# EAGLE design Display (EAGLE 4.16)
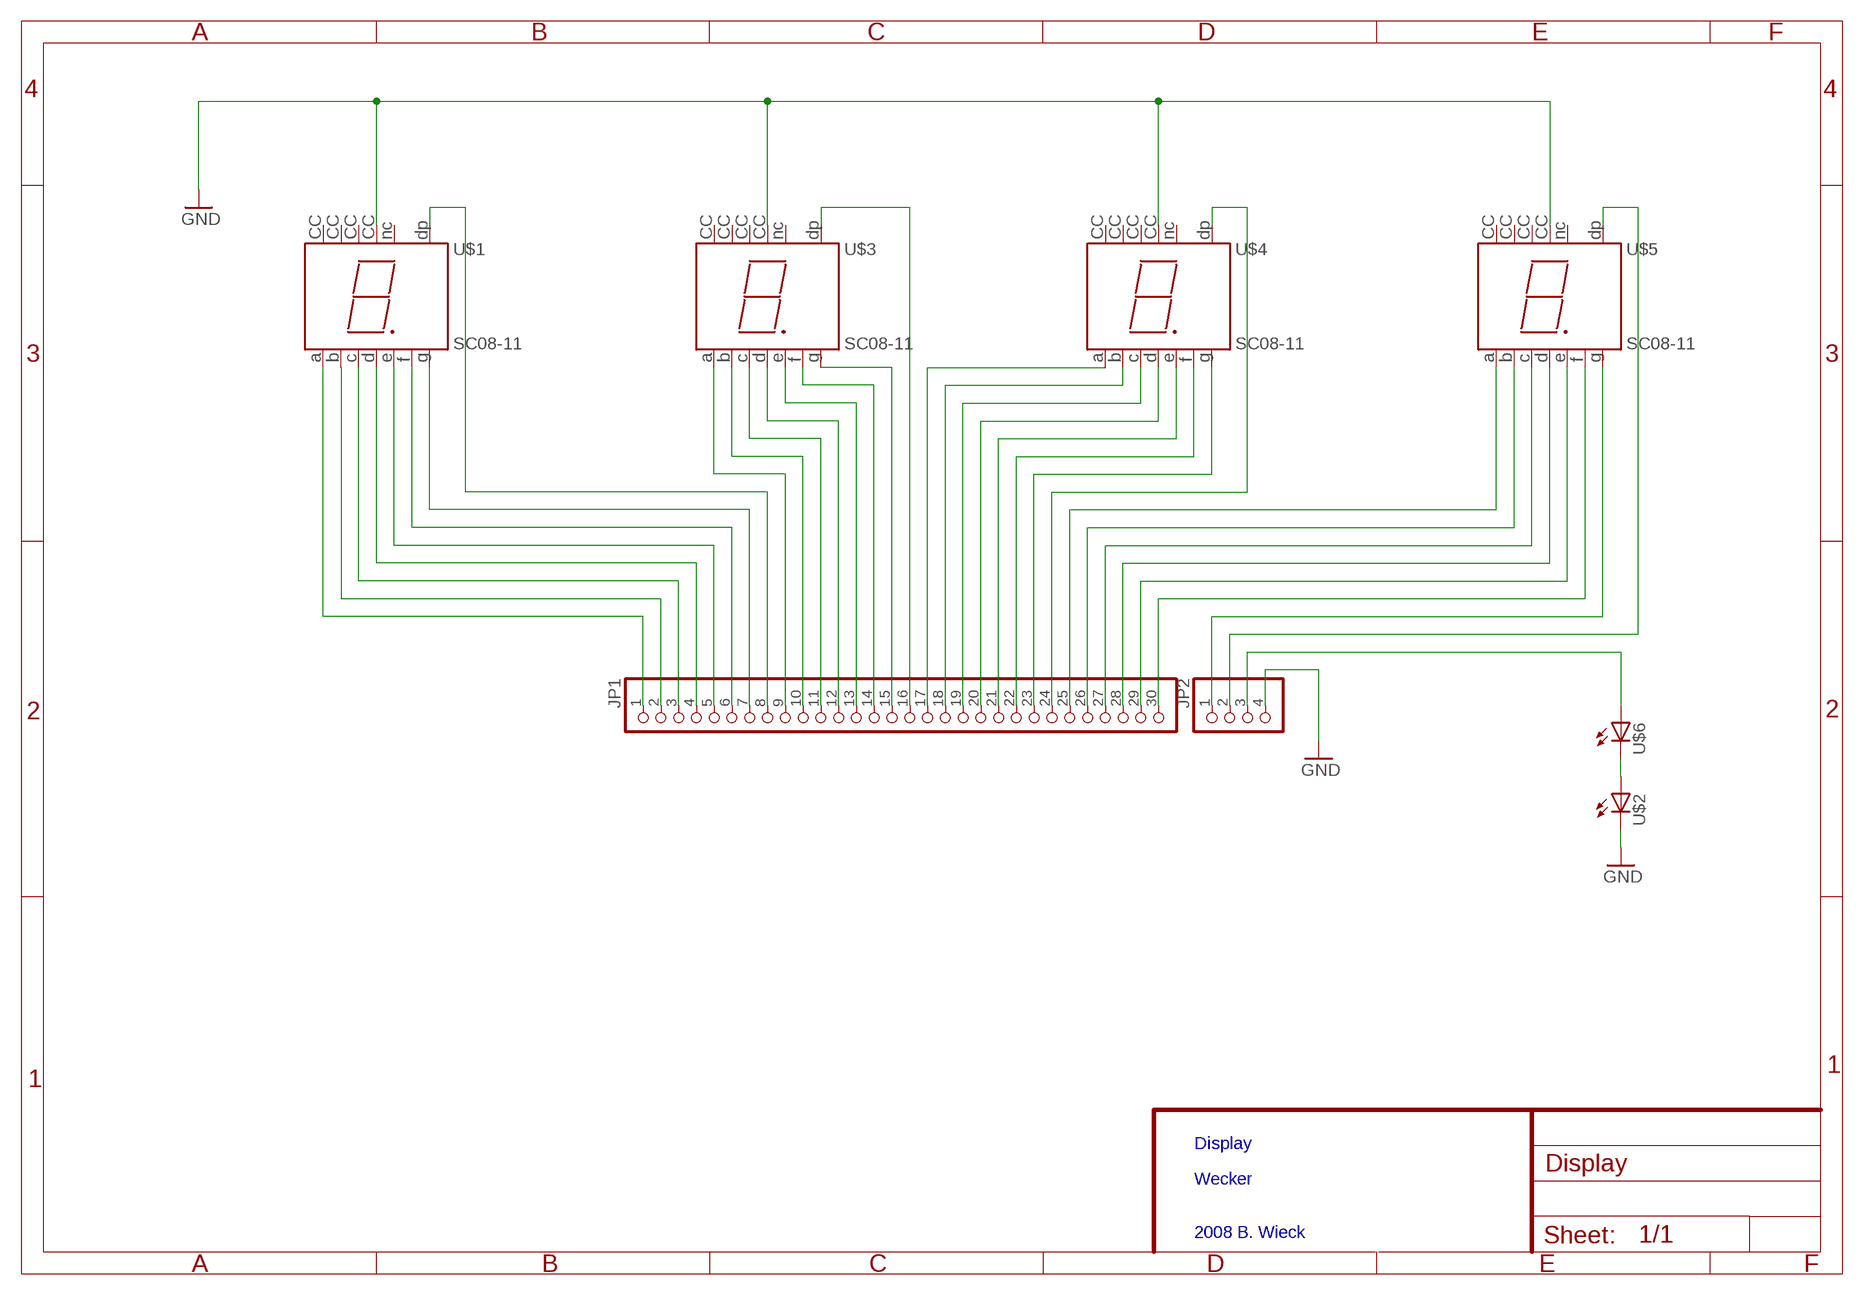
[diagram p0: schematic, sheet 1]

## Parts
JP1  PINHD-1X30  [1X30]
JP2  PINHD-1X4  [1X04]
U$1  SC08-11  [SC08]
U$2  LED3MM  [LED3MM]
U$3  SC08-11  [SC08]
U$4  SC08-11  [SC08]
U$5  SC08-11  [SC08]
U$6  LED3MM  [LED3MM]

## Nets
GND: JP2.4 U$1.CC@3(CC) U$2.K(C) U$3.CC@3(CC) U$4.CC@3(CC) U$5.CC@3(CC)
N$1: JP1.1 U$1.A
N$2: JP1.2 U$1.B
N$3: JP1.3 U$1.C
N$4: JP1.4 U$1.D
N$5: JP1.5 U$1.E
N$6: JP1.6 U$1.F
N$7: JP1.7 U$1.G
N$8: JP1.8 U$1.DP
N$9: JP1.9 U$3.A
N$10: JP1.10 U$3.B
N$11: JP1.11 U$3.C
N$12: JP1.12 U$3.D
N$13: JP1.13 U$3.E
N$14: JP1.14 U$3.F
N$15: JP1.15 U$3.G
N$16: JP1.16 U$3.DP
N$17: JP1.17 U$4.A
N$18: JP1.18 U$4.B
N$19: JP1.19 U$4.C
N$20: JP1.20 U$4.D
N$21: JP1.21 U$4.E
N$22: JP1.22 U$4.F
N$23: JP1.23 U$4.G
N$24: JP1.24 U$4.DP
N$25: JP1.25 U$5.A
N$26: JP1.26 U$5.B
N$27: JP1.27 U$5.C
N$28: JP1.28 U$5.D
N$29: JP1.29 U$5.E
N$30: JP1.30 U$5.F
N$31: JP2.1 U$5.G
N$32: JP2.2 U$5.DP
N$33: JP2.3 U$6.A
N$35: U$2.A U$6.K(C)
Unconnected: U$1.CC U$1.CC@1(CC) U$1.CC@2(CC) U$1.NC U$3.CC U$3.CC@1(CC) U$3.CC@2(CC) U$3.NC U$4.CC U$4.CC@1(CC) U$4.CC@2(CC) U$4.NC U$5.CC U$5.CC@1(CC) U$5.CC@2(CC) U$5.NC

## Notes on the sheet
- Display
- Wecker
- 2008 B. Wieck

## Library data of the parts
JP1 = pinhead:PINHD-1X30: PIN HEADER
JP2 = pinhead:PINHD-1X4: PIN HEADER
U$1 U$3-U$5 = kingbright:SC08-11
U$2 U$6 = led:LED: LED

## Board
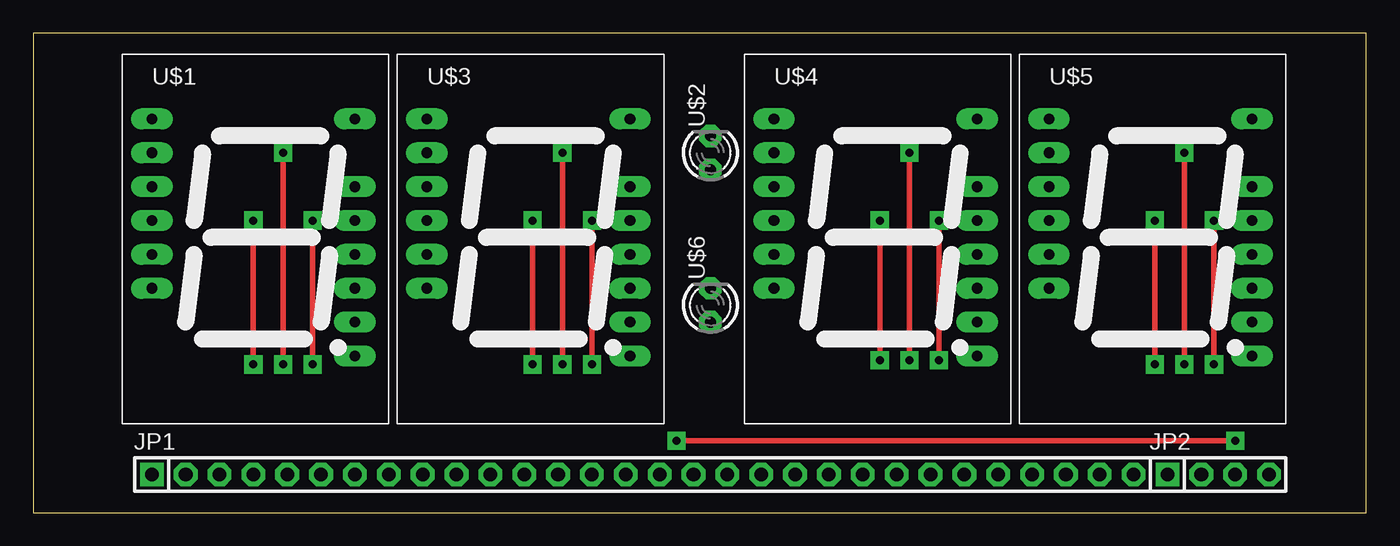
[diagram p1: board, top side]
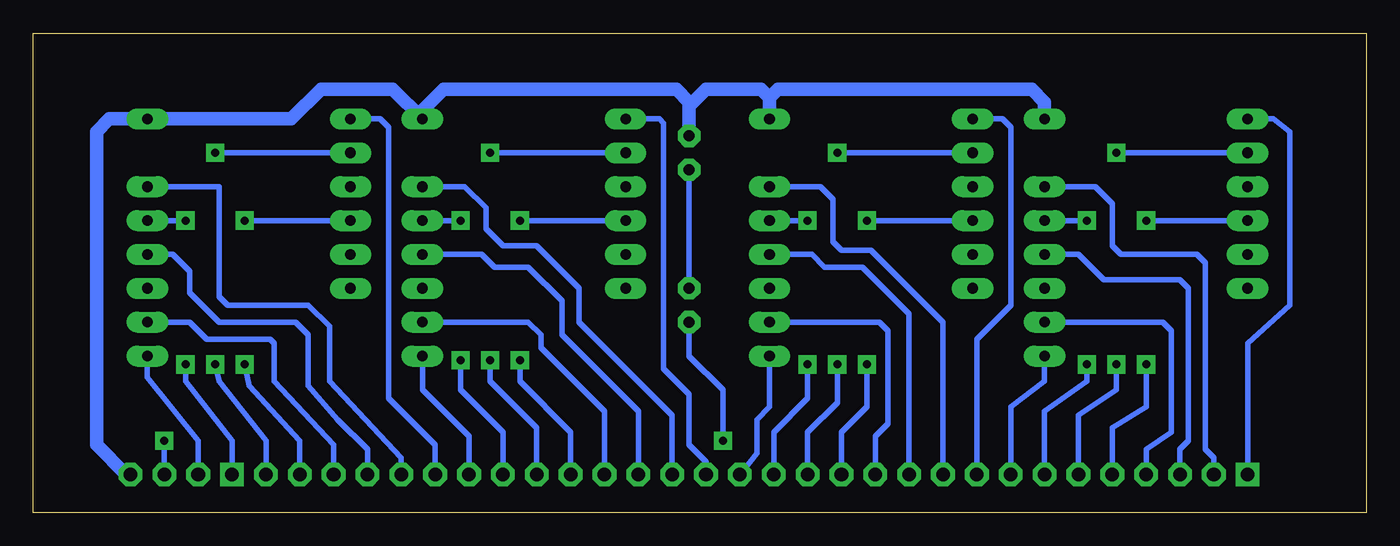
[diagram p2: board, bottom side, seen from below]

Size 100 x 35.95 mm. Coordinates in mm from the lower left corner, seen from the top.
Outline: 0,0 100,0 100,35.95 0,35.95 0,0
Copper layers (1*16): Top 0.035mm / dielectric 1.5mm / Bottom 0.035mm
Design rules "BWieck": minimum track width 12mil, minimum drill 24mil, track to track 12mil, track to pad 12mil, pad to pad 10mil, via to via 12mil, smd to smd 8mil, copper to edge 40mil, drill to drill 8mil, minimum pad ring 15mil, minimum via ring 15mil, stop-mask expansion 4mil, vias tented up to drill 0mil, thermal gap 10mil

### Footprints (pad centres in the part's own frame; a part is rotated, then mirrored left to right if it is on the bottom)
1X30 = drill 1.016 square: 1 -36.83,0 | drill 1.016 octagon: 2 -34.29,0; 3 -31.75,0; 4 -29.21,0; 5 -26.67,0; 6 -24.13,0; 7 -21.59,0; 8 -19.05,0; 9 -16.51,0; 10 -13.97,0; 11 -11.43,0; 12 -8.89,0; 13 -6.35,0; 14 -3.81,0; 15 -1.27,0; 16 1.27,0; 17 3.81,0; 18 6.35,0; 19 8.89,0; 20 11.43,0; 21 13.97,0; 22 16.51,0; 23 19.05,0; 24 21.59,0; 25 24.13,0; 26 26.67,0; 27 29.21,0; 28 31.75,0; 29 34.29,0; 30 36.83,0
1X04 = drill 1.016 square: 1 -3.81,0 | drill 1.016 octagon: 2 -1.27,0; 3 1.27,0; 4 3.81,0
SC08 = drill 0.8 long: A -17.78,22.86; B -2.54,17.78; C -2.54,12.7; CC -17.78,17.78; CC@1 -17.78,12.7; CC@2 -2.54,10.16; CC@3 -2.54,22.86; D -2.54,7.62; DP -2.54,5.08; E -17.78,15.24; F -17.78,20.32; G -2.54,15.24; NC -17.78,10.16
LED3MM = drill 0.813 pad 1.676 octagon: A -1.27,0; K 1.27,0

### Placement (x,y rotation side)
JP1  45.72,2.86 0 top
JP2  88.9,2.86 0 top
U$1  26.67,6.67 0 top
U$2  50.8,26.99 90 top
U$3  47.31,6.67 0 top
U$4  73.34,6.67 0 top
U$5  93.98,6.67 0 top
U$6  50.8,15.56 90 top

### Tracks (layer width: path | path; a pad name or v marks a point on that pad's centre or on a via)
GND
  Bottom 1.016: JP2.4 93.03,2.86 95.25,5.08 95.25,28.57 94.3,29.53 U$5.CC@3 80.64,29.53 78.42,31.75 73.03,31.75 U$4.CC@3 70.8,30.16 69.22,31.75 51.75,31.75 50.8,30.8 U$2.K 50.8,30.48 49.53,31.75 45.4,31.75 44.77,31.12 | U$3.CC@3 44.77,31.12 | 44.77,31.12 44.13,31.75 25.08,31.75 24.13,30.8 U$1.CC@3
N$1
  Bottom 0.406: JP1.1 8.89,12.7 5.71,15.56 5.71,28.57 6.99,29.53 U$1.A
N$2
  Bottom 0.406: JP1.2 11.43,4.13 12.06,4.76 12.06,18.73 12.7,19.37 18.41,19.37 19.05,20 19.05,23.18 20.32,24.45 U$1.B
N$3
  Bottom 0.406: JP1.3 13.97,4.76 13.34,5.4 13.34,16.83 13.97,17.46 19.68,17.46 21.59,19.37 U$1.C
N$4
  Bottom 0.406: JP1.4 16.51,4.76 14.61,6.03 14.61,13.65 15.24,14.29 U$1.D
N$5  (via drill 0.6)
  Top 0.406: v16.51,11.11 v16.51,21.91
  Bottom 0.406: JP1.5 19.05,6.35 16.51,7.94 v16.51,11.11 | v16.51,21.91 U$1.E
N$6  (via drill 0.6)
  Top 0.406: v18.73,11.11 v18.73,26.99
  Bottom 0.406: JP1.6 21.59,7.3 18.73,9.21 v18.73,11.11 | v18.73,26.99 U$1.F
N$7  (via drill 0.6)
  Top 0.406: v20.95,11.11 v20.95,21.91
  Bottom 0.406: JP1.7 24.13,7.62 20.95,9.84 v20.95,11.11 | v20.95,21.91 U$1.G
N$8
  Bottom 0.406: JP1.8 26.67,7.94 24.13,9.84 U$1.DP
N$9
  Bottom 0.406: JP1.9 29.21,13.02 26.67,15.56 26.67,28.89 27.3,29.53 U$3.A 29.84,29.53
N$10
  Bottom 0.406: JP1.10 31.75,14.29 37.15,19.68 39.37,19.68 40.01,20.32 40.01,23.49 40.96,24.45 44.45,24.45 44.77,24.77 U$3.B
N$11
  Bottom 0.406: JP1.11 34.29,14.92 37.78,18.42 40.64,18.42 41.59,19.37 U$3.C
N$12
  Bottom 0.406: JP1.12 36.83,5.71 35.88,6.67 35.88,13.65 36.51,14.29 44.45,14.29 44.77,14.6 U$3.D
N$13  (via drill 0.6)
  Top 0.406: v37.47,11.11 v37.47,21.91
  Bottom 0.406: JP1.13 39.37,6.03 37.47,7.94 v37.47,11.11 | v37.47,21.91 U$3.E
N$14  (via drill 0.6)
  Top 0.406: v39.69,11.11 v39.69,26.99
  Bottom 0.406: JP1.14 41.91,6.03 39.69,8.25 v39.69,11.11 | U$3.F 29.53,26.67 29.84,26.99 v39.69,26.99
N$15  (via drill 0.6)
  Top 0.406: v41.91,11.11 v41.91,21.91
  Bottom 0.406: JP1.15 44.45,6.03 41.91,8.57 v41.91,11.11 | U$3.G 44.77,21.59 44.45,21.91 v41.91,21.91
N$16
  Bottom 0.406: JP1.16 45.72,4.45 45.72,6.99 44.77,7.94 44.77,11.43 44.45,11.75 U$3.DP
N$17
  Bottom 0.406: JP1.17 49.53,3.81 50.8,5.08 50.8,8.89 52.7,10.79 52.7,29.21 53.02,29.53 U$4.A
N$18
  Bottom 0.406: JP1.18 52.07,7.3 59.05,14.29 59.05,16.83 62.23,20 64.77,20 66.04,21.27 66.04,22.86 67.63,24.45 U$4.B
N$19
  Bottom 0.406: JP1.19 54.61,7.62 60.33,13.34 60.33,15.88 62.87,18.42 65.41,18.42 66.36,19.37 U$4.C
N$20
  Bottom 0.406: JP1.20 57.15,7.62 61.91,12.38 61.91,13.34 62.87,14.29 U$4.D
N$21  (via drill 0.6)
  Top 0.406: v63.5,11.43 v63.5,21.91
  Bottom 0.406: JP1.21 59.69,6.03 63.5,9.84 v63.5,11.43 | v63.5,21.91 U$4.E
N$22  (via drill 0.6)
  Top 0.406: v65.72,11.43 v65.72,26.99
  Bottom 0.406: JP1.22 62.23,6.35 65.72,9.84 v65.72,11.43 | v65.72,26.99 U$4.F
N$23  (via drill 0.6)
  Top 0.406: v67.94,11.43 v67.94,21.91
  Bottom 0.406: JP1.23 64.77,6.03 67.94,9.21 v67.94,11.43 | v67.94,21.91 U$4.G
N$24
  Bottom 0.406: JP1.24 67.31,5.71 70.8,9.21 U$4.DP
N$25
  Bottom 0.406: JP1.25 69.85,5.08 73.34,8.57 73.34,28.89 73.98,29.53 U$5.A
N$26
  Bottom 0.406: JP1.26 72.39,4.13 77.79,9.84 77.79,13.97 79.38,15.56 85.41,15.56 86.04,16.19 86.04,24.45 91.12,24.45 91.44,24.77 U$5.B
N$27
  Bottom 0.406: JP1.27 74.93,4.76 77.15,6.99 79.38,9.53 79.38,13.34 80.33,14.29 86.04,14.29 88.27,16.51 88.27,18.1 89.53,19.37 U$5.C
N$28
  Bottom 0.406: JP1.28 77.47,5.08 81.92,9.84 81.92,12.7 82.23,13.02 87,13.02 88.27,14.29 U$5.D
N$29  (via drill 0.6)
  Top 0.406: v84.14,11.11 v84.14,21.91
  Bottom 0.406: JP1.29 80.01,5.4 83.82,9.53 v84.14,11.11 | v84.14,21.91 U$5.E
N$30  (via drill 0.6)
  Top 0.406: v86.36,11.11 v86.36,26.99
  Bottom 0.406: JP1.30 82.55,5.4 86.04,9.84 v86.36,11.11 | v86.36,26.99 U$5.F
N$31  (via drill 0.6)
  Top 0.406: v88.58,11.11 v88.58,21.91
  Bottom 0.406: JP2.1 85.09,5.4 88.58,9.84 v88.58,11.11 | v88.58,21.91 U$5.G
N$32
  Bottom 0.406: JP2.2 87.63,5.4 91.44,10.16 U$5.DP
N$33  (via drill 0.6)
  Top 0.406: v90.17,5.4 v48.26,5.4
  Bottom 0.406: JP2.3 v90.17,5.4 | v48.26,5.4 48.26,9.21 50.8,11.75 U$6.A
N$35
  Bottom 0.406: U$2.A 51.12,25.72 50.8,25.4 U$6.K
